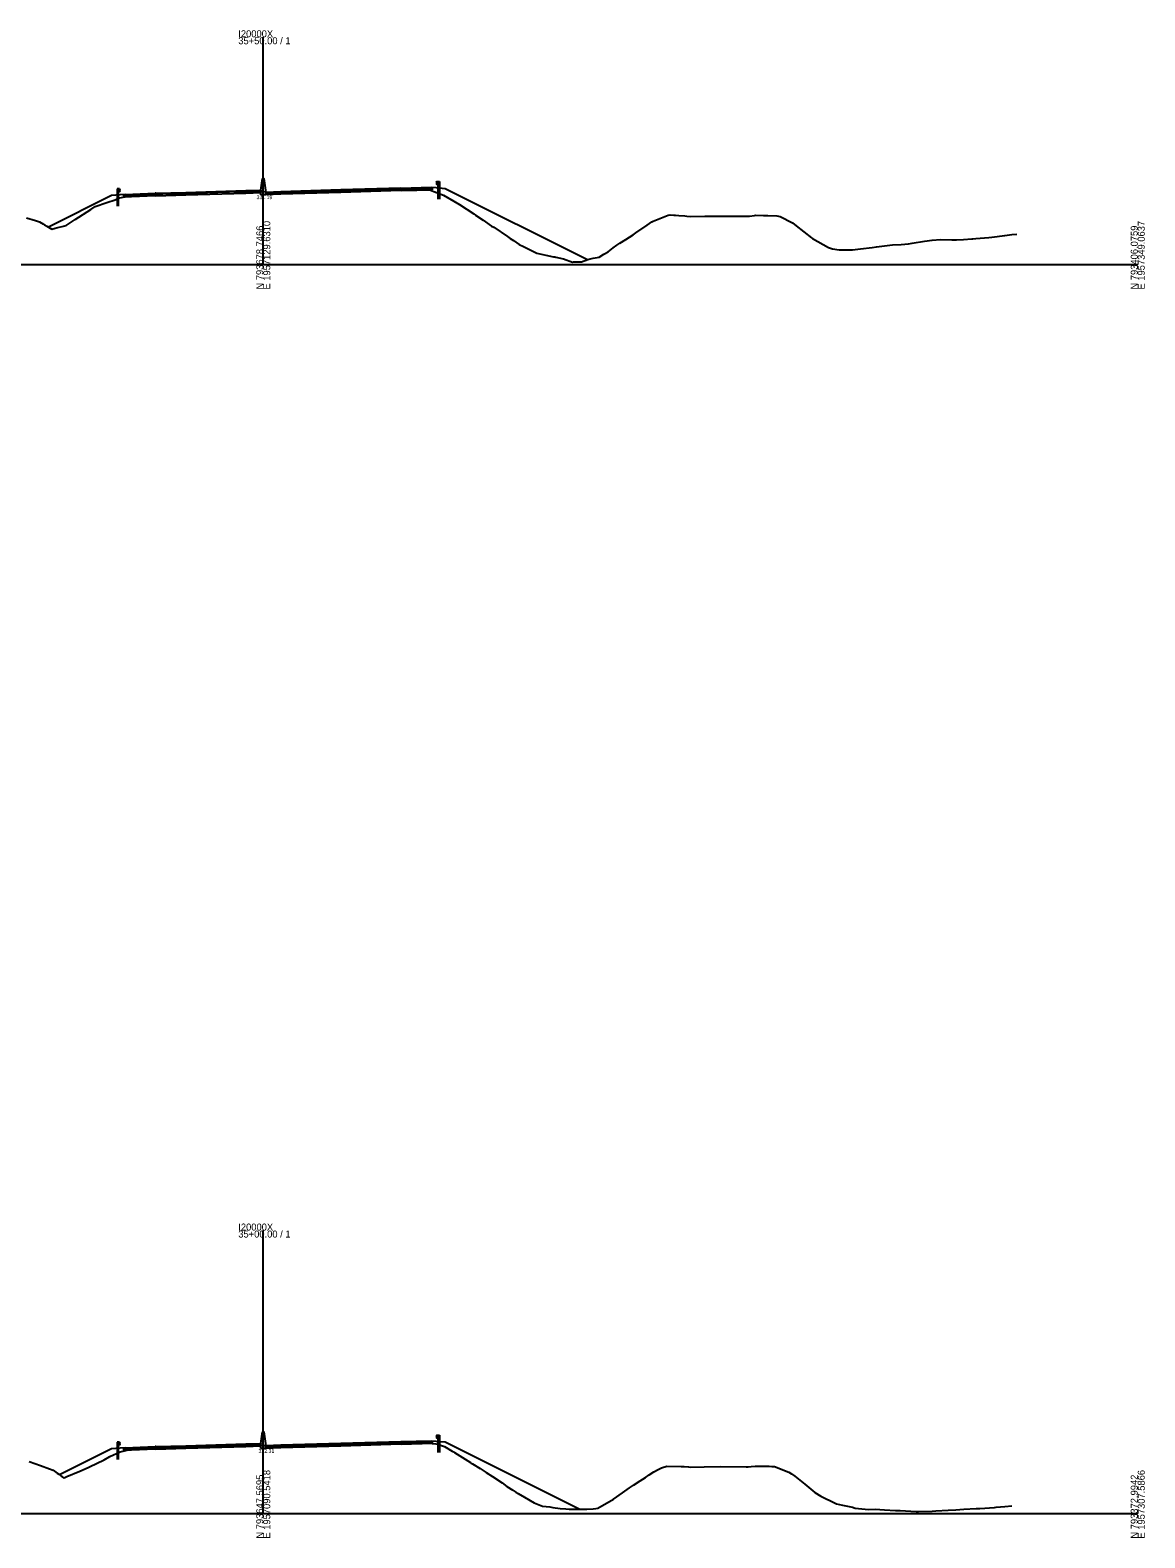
# Model space of a CAD drawing. Extents: x -4026 to 9638, y -10 to 19609.
# Drawn here: x -2743 to -2297, y 4990 to 5594 of the extents above; entities that cross this region are included whole.
import ezdxf

# ---------------------------------------------------------------- set-up
doc = ezdxf.new("R2010")
doc.units = 0
for name, color, linetype in [('RD_GPK_XS_Cell', 7, 'Continuous'), ('RD_XS_Base', 7, 'Continuous'), ('RD_XS_ExGround', 7, 'Continuous'), ('RD_XS_GR', 7, 'Continuous'), ('RD_XS_Greenside', 7, 'Continuous'), ('RD_XS_MedBWall', 7, 'Continuous'), ('RD_XS_Pave', 7, 'Continuous'), ('RD_XS_PaveOvlay', 7, 'Continuous'), ('RD_XS_TX_Elev_EX', 7, 'Continuous')]:
    doc.layers.add(name, color=color, linetype=linetype)

msp = doc.modelspace()

# ---------------------------------------------------------------- linework, layer by layer
at = {"layer": 'RD_GPK_XS_Cell'}
for p, q in [((-2650, 5500), (-2650, 5591)), ((-3000, 5500), (-2650, 5500)), ((-2650, 5500), (-2300, 5500)), ((-2650, 5000), (-2650, 5113.32)), ((-3000, 5000), (-2650, 5000)), ((-2650, 5000), (-2300, 5000))]:
    msp.add_line(p, q, dxfattribs=at)
at = {"layer": 'RD_XS_Base'}
for points in [[(-2657, 5529.29), (-2681, 5528.58), (-2693, 5528.21)], [(-2693, 5527.54), (-2681, 5527.91), (-2657, 5528.62)], [(-2651, 5529.48), (-2657, 5529.29)], [(-2657, 5529.29), (-2657, 5528.62)], [(-2657, 5528.62), (-2651, 5528.81)], [(-2651, 5528.81), (-2651, 5529.48)], [(-2649, 5528.58), (-2643, 5528.82)], [(-2649, 5527.91), (-2649, 5528.58)], [(-2643, 5528.82), (-2619, 5529.55), (-2595, 5530.26)], [(-2595, 5529.59), (-2619, 5528.88), (-2643, 5528.15)], [(-2643, 5528.15), (-2643, 5528.82)], [(-2595, 5530.26), (-2594.75, 5530.27)], [(-2595, 5529.59), (-2595, 5530.26)], [(-2594.75, 5529.6), (-2595, 5529.59)], [(-2582.25, 5530.65), (-2582.75, 5530.63), (-2594.75, 5530.27)], [(-2594.75, 5530.27), (-2594.75, 5529.6)], [(-2594.75, 5529.6), (-2582.25, 5529.98)], [(-2582.25, 5529.98), (-2582.25, 5530.65)], [(-2705.75, 5527.71), (-2705.25, 5527.73), (-2693.25, 5528.2)], [(-2705.75, 5527.04), (-2705.75, 5527.71)], [(-2693.25, 5527.53), (-2705.75, 5527.04)], [(-2693.25, 5528.2), (-2693, 5528.21)], [(-2693.25, 5527.53), (-2693.25, 5528.2)], [(-2693, 5527.54), (-2693.25, 5527.53)], [(-2693, 5528.21), (-2693, 5527.54)], [(-2643, 5528.15), (-2649, 5527.91)], [(-2657, 5027.57), (-2681, 5026.85), (-2693, 5026.48)], [(-2651, 5027.75), (-2657, 5027.57)], [(-2657, 5027.57), (-2657, 5026.9)], [(-2651, 5027.08), (-2651, 5027.75)], [(-2643, 5027.02), (-2619, 5027.74), (-2595, 5028.46)], [(-2595, 5027.79), (-2619, 5027.07), (-2643, 5026.35)], [(-2595, 5028.46), (-2594.75, 5028.47)], [(-2595, 5027.79), (-2595, 5028.46)], [(-2594.75, 5027.8), (-2595, 5027.79)], [(-2582.25, 5028.85), (-2582.75, 5028.83), (-2594.75, 5028.47)], [(-2594.75, 5028.47), (-2594.75, 5027.8)], [(-2594.75, 5027.8), (-2582.25, 5028.18)], [(-2582.25, 5028.18), (-2582.25, 5028.85)], [(-2705.75, 5025.98), (-2705.25, 5026), (-2693.25, 5026.48)], [(-2705.75, 5025.31), (-2705.75, 5025.98)], [(-2693.25, 5025.81), (-2705.75, 5025.31)], [(-2693.25, 5026.48), (-2693, 5026.48)], [(-2693.25, 5025.81), (-2693.25, 5026.48)], [(-2693, 5025.81), (-2693.25, 5025.81)], [(-2693, 5025.81), (-2681, 5026.18), (-2657, 5026.9)], [(-2693, 5026.48), (-2693, 5025.81)], [(-2657, 5026.9), (-2651, 5027.08)], [(-2649, 5026.78), (-2643, 5027.02)], [(-2649, 5026.11), (-2649, 5026.78)], [(-2643, 5026.35), (-2649, 5026.11)], [(-2643, 5026.35), (-2643, 5027.02)]]:
    msp.add_lwpolyline(points, dxfattribs=at)
at = {"layer": 'RD_XS_ExGround'}
for points in [[(-2744.73, 5518.7), (-2741.2, 5517.64), (-2739.6, 5517.08), (-2737.97, 5516.17), (-2737.5, 5515.88), (-2736.65, 5515.37), (-2734.57, 5514.12), (-2733.26, 5514.52), (-2728.94, 5515.68), (-2725.25, 5518), (-2719.06, 5522.08), (-2717.28, 5523.25), (-2712.64, 5524.9), (-2709.3, 5525.9), (-2707.6, 5526.75), (-2704.43, 5527.23), (-2703.33, 5527.4), (-2700.91, 5527.8), (-2700.05, 5527.93), (-2692.06, 5528.25), (-2690.7, 5528.3), (-2690.19, 5528.31), (-2679.86, 5528.61), (-2672.38, 5528.86), (-2668.24, 5528.99), (-2665.63, 5529.06), (-2663.5, 5529.11), (-2656.48, 5529.29), (-2654.34, 5529.28), (-2650.92, 5529.27), (-2650, 5529.19), (-2647.75, 5528.98), (-2646.99, 5528.9), (-2645.36, 5529.01), (-2641.8, 5529.23), (-2639.49, 5529.31), (-2638.29, 5529.35), (-2637.76, 5529.37), (-2637.46, 5529.38), (-2635.63, 5529.44), (-2630.32, 5529.55), (-2629.82, 5529.56), (-2618.59, 5529.87), (-2607.58, 5530.16), (-2603.85, 5530.22), (-2598.52, 5530.31), (-2592.56, 5530.33), (-2590.25, 5530.33), (-2588.86, 5530.22), (-2586.68, 5530.04), (-2585.73, 5529.98), (-2583.13, 5529.78), (-2581.7, 5529.31), (-2577.87, 5527.77), (-2573.73, 5525.43), (-2571.45, 5524.05), (-2565.75, 5520.29), (-2565.03, 5519.79), (-2562.05, 5517.8), (-2558.61, 5515.41), (-2557.78, 5514.98), (-2552.19, 5511.29), (-2551.13, 5510.5), (-2549.8, 5509.58), (-2547.57, 5508.05), (-2545.78, 5507.2), (-2544.02, 5506.35), (-2541.83, 5505.26), (-2540.46, 5504.61), (-2539.36, 5504.31), (-2536.9, 5503.72), (-2533.85, 5503.16), (-2533.35, 5503.07), (-2532.94, 5502.97), (-2529.79, 5502.29), (-2526.23, 5501.01), (-2525.88, 5501.06), (-2522.68, 5501.04), (-2520.1, 5502), (-2519.12, 5502.27), (-2517.9, 5502.56), (-2515.57, 5503.01), (-2513.69, 5504.13), (-2512.01, 5505.15), (-2509.93, 5506.74), (-2508.45, 5507.83), (-2507.27, 5508.52), (-2504.9, 5510.03), (-2501.95, 5511.97), (-2500.85, 5512.74), (-2496.31, 5515.8), (-2494.43, 5517.07), (-2493.98, 5517.35), (-2488.01, 5519.74), (-2487.12, 5519.86), (-2485.62, 5519.76), (-2485.01, 5519.73), (-2483.67, 5519.62), (-2481.27, 5519.48), (-2480.42, 5519.41), (-2478.88, 5519.26), (-2473.33, 5519.34), (-2466.87, 5519.44), (-2458.55, 5519.36), (-2455.44, 5519.34), (-2453.43, 5519.67), (-2452.82, 5519.76), (-2449.77, 5519.67), (-2448.11, 5519.66), (-2444.44, 5519.58), (-2443.09, 5519.25), (-2438.15, 5516.76), (-2436.67, 5515.57), (-2430.57, 5510.73), (-2430.18, 5510.42), (-2423.83, 5506.84), (-2422.2, 5506.3), (-2419.55, 5505.91), (-2417.42, 5505.85), (-2414.23, 5505.96), (-2411, 5506.33), (-2406.25, 5506.88), (-2404.58, 5507.15), (-2398.16, 5507.85), (-2394.66, 5508.09), (-2391.74, 5508.34), (-2390.3, 5508.53), (-2385.33, 5509.33), (-2382.32, 5509.82), (-2378.91, 5510), (-2374.35, 5509.87), (-2372.49, 5509.93), (-2369.76, 5510.05), (-2366.37, 5510.33), (-2366.07, 5510.35), (-2364.82, 5510.46), (-2359.65, 5510.88), (-2358.4, 5510.99), (-2353.24, 5511.7), (-2350.42, 5512.04), (-2348.43, 5512.23)], [(-2743.68, 5020.83), (-2739.2, 5019.28), (-2735.61, 5017.89), (-2734.06, 5017.34), (-2732.46, 5016.21), (-2731.87, 5015.75), (-2730.56, 5014.93), (-2729.71, 5014.37), (-2728.67, 5014.81), (-2723.38, 5016.98), (-2720.08, 5018.53), (-2719.49, 5018.8), (-2713.71, 5021.6), (-2711.43, 5022.82), (-2707.34, 5024.78), (-2703.28, 5025.7), (-2702.52, 5025.81), (-2700.97, 5026.03), (-2700.06, 5026.15), (-2692.95, 5026.4), (-2690.99, 5026.46), (-2687.96, 5026.56), (-2680.17, 5026.82), (-2673.05, 5027.04), (-2668.39, 5027.17), (-2666.24, 5027.23), (-2656.66, 5027.48), (-2654.76, 5027.46), (-2651.19, 5027.42), (-2650, 5027.31), (-2649.11, 5027.23), (-2647.24, 5027.07), (-2644.34, 5027.25), (-2642.08, 5027.39), (-2641.37, 5027.42), (-2634.39, 5027.65), (-2631.13, 5027.72), (-2630.17, 5027.74), (-2628.16, 5027.8), (-2618.98, 5028.07), (-2615.3, 5028.17), (-2607.79, 5028.34), (-2599.96, 5028.49), (-2598.43, 5028.52), (-2597, 5028.53), (-2590.45, 5028.56), (-2589.33, 5028.48), (-2587.96, 5028.4), (-2584.55, 5028.19), (-2582.42, 5028.06), (-2580.99, 5027.98), (-2579.87, 5027.65), (-2577.43, 5026.83), (-2574.36, 5025.01), (-2573.87, 5024.73), (-2573.49, 5024.48), (-2570.32, 5022.48), (-2567.12, 5020.47), (-2566.76, 5020.25), (-2566.29, 5019.95), (-2563.2, 5018.1), (-2560.75, 5016.4), (-2558.23, 5014.85), (-2554.37, 5012.29), (-2552.52, 5010.86), (-2550.17, 5009.34), (-2548.96, 5008.6), (-2548, 5008.08), (-2545.4, 5006.59), (-2541.63, 5004.26), (-2538.28, 5003.05), (-2535.25, 5002.67), (-2534.04, 5002.51), (-2531.16, 5002.1), (-2528.88, 5001.96), (-2527.6, 5001.81), (-2525.98, 5001.79), (-2522.51, 5001.73), (-2520.48, 5001.8), (-2517.92, 5001.87), (-2516.92, 5002.01), (-2516.13, 5002.2), (-2509.76, 5005.84), (-2506.24, 5008.34), (-2503.39, 5010.39), (-2502.68, 5010.85), (-2501.79, 5011.43), (-2499.12, 5013.1), (-2497.01, 5014.53), (-2495.56, 5015.49), (-2493.73, 5016.69), (-2492, 5017.73), (-2490.64, 5018.31), (-2488.44, 5019), (-2482.69, 5018.93), (-2481.5, 5018.93), (-2479.85, 5018.75), (-2479.09, 5018.66), (-2473.47, 5018.75), (-2467.1, 5018.86), (-2456.68, 5018.78), (-2455.87, 5018.77), (-2454.7, 5018.87), (-2453.06, 5019.01), (-2451.66, 5018.99), (-2447.47, 5018.95), (-2446.47, 5018.93), (-2445.73, 5018.92), (-2445.35, 5018.83), (-2439.65, 5016.63), (-2438.61, 5015.93), (-2437.29, 5014.94), (-2433.28, 5011.8), (-2429.23, 5008.47), (-2426.9, 5007.01), (-2421.16, 5004.2), (-2420.53, 5003.89), (-2418.14, 5003.41), (-2414.16, 5002.54), (-2413.1, 5002.24), (-2407.78, 5001.61), (-2405.04, 5001.73), (-2401.41, 5001.54), (-2396.97, 5001.31), (-2395.04, 5001.22), (-2388.66, 5000.85), (-2387.72, 5000.87), (-2382.29, 5000.94), (-2380.85, 5001.08), (-2375.92, 5001.45), (-2372.79, 5001.56), (-2369.54, 5001.84), (-2364.72, 5002.03), (-2363.17, 5002.08), (-2357.3, 5002.48), (-2356.66, 5002.53), (-2353.18, 5002.83), (-2350.42, 5003.15)]]:
    msp.add_lwpolyline(points, dxfattribs=at)
at = {"layer": 'RD_XS_GR'}
for points in [[(-2707.98, 5530.3), (-2708.48, 5530.3)], [(-2708.48, 5530.3), (-2708.48, 5527.8)], [(-2707.98, 5527.84), (-2707.98, 5530.3)], [(-2707.49, 5530.3), (-2707.98, 5530.3)], [(-2707.98, 5530.3), (-2707.98, 5529.12)], [(-2707.98, 5529.12), (-2707.49, 5529.12)], [(-2707.49, 5530.3), (-2707.25, 5530)], [(-2707.49, 5529.12), (-2707.49, 5530.3)], [(-2707.25, 5529.42), (-2707.49, 5529.12)], [(-2707.25, 5530), (-2707.48, 5529.7)], [(-2707.48, 5529.7), (-2707.25, 5529.42)], [(-2580.51, 5533.2), (-2580.75, 5532.9)], [(-2580.75, 5532.9), (-2580.52, 5532.6)], [(-2580.52, 5532.6), (-2580.75, 5532.32)], [(-2580.75, 5532.32), (-2580.51, 5532.02)], [(-2580.51, 5532.02), (-2580.51, 5533.2)], [(-2580.51, 5533.2), (-2580.02, 5533.2)], [(-2580.02, 5532.02), (-2580.51, 5532.02)], [(-2580.02, 5533.2), (-2579.52, 5533.2)], [(-2580.02, 5530.74), (-2580.02, 5533.2)], [(-2580.02, 5533.2), (-2580.02, 5532.02)], [(-2580.02, 5526.24), (-2580.02, 5530.74)], [(-2580.02, 5530.74), (-2579.52, 5530.7)], [(-2579.52, 5530.7), (-2580.02, 5530.74)], [(-2579.52, 5533.2), (-2579.52, 5530.7)], [(-2579.52, 5530.7), (-2579.52, 5526.24)], [(-2707.98, 5527.84), (-2708.48, 5527.8)], [(-2708.48, 5527.8), (-2707.98, 5527.84)], [(-2708.48, 5527.8), (-2708.48, 5523.34)], [(-2707.98, 5523.34), (-2707.98, 5527.84)], [(-2707.98, 5028.58), (-2708.48, 5028.58)], [(-2708.48, 5028.58), (-2708.48, 5026.08)], [(-2707.98, 5026.12), (-2707.98, 5028.58)], [(-2707.49, 5028.58), (-2707.98, 5028.58)], [(-2707.98, 5028.58), (-2707.98, 5027.4)], [(-2707.49, 5028.58), (-2707.25, 5028.28)], [(-2707.49, 5027.4), (-2707.49, 5028.58)], [(-2707.25, 5027.7), (-2707.49, 5027.4)], [(-2707.25, 5028.28), (-2707.48, 5027.98)], [(-2707.48, 5027.98), (-2707.25, 5027.7)], [(-2580.51, 5031.4), (-2580.75, 5031.1)], [(-2580.75, 5031.1), (-2580.52, 5030.8)], [(-2580.52, 5030.8), (-2580.75, 5030.52)], [(-2580.75, 5030.52), (-2580.51, 5030.22)], [(-2580.51, 5030.22), (-2580.51, 5031.4)], [(-2580.51, 5031.4), (-2580.02, 5031.4)], [(-2580.02, 5030.22), (-2580.51, 5030.22)], [(-2580.02, 5031.4), (-2579.52, 5031.4)], [(-2580.02, 5028.94), (-2580.02, 5031.4)], [(-2580.02, 5031.4), (-2580.02, 5030.22)], [(-2580.02, 5024.44), (-2580.02, 5028.94)], [(-2580.02, 5028.94), (-2579.52, 5028.9)], [(-2579.52, 5028.9), (-2580.02, 5028.94)], [(-2579.52, 5031.4), (-2579.52, 5028.9)], [(-2579.52, 5028.9), (-2579.52, 5024.44)], [(-2707.98, 5026.12), (-2708.48, 5026.08)], [(-2708.48, 5026.08), (-2707.98, 5026.12)], [(-2708.48, 5026.08), (-2708.48, 5021.62)], [(-2707.98, 5027.4), (-2707.49, 5027.4)], [(-2707.98, 5021.62), (-2707.98, 5026.12)]]:
    msp.add_lwpolyline(points, dxfattribs=at)
at = {"layer": 'RD_XS_Greenside'}
for points in [[(-2582.75, 5530.97), (-2580.75, 5530.8)], [(-2580.75, 5530.8), (-2577.25, 5530.51), (-2520.18, 5501.97)], [(-2707.25, 5527.9), (-2710.75, 5527.62), (-2736.01, 5514.99)], [(-2705.25, 5528.06), (-2707.25, 5527.9)], [(-2582.75, 5029.17), (-2580.75, 5029)], [(-2580.75, 5029), (-2577.25, 5028.71), (-2523.33, 5001.75)], [(-2707.25, 5026.18), (-2710.75, 5025.9), (-2731.5, 5015.52)], [(-2705.25, 5026.34), (-2707.25, 5026.18)]]:
    msp.add_lwpolyline(points, dxfattribs=at)
at = {"layer": 'RD_XS_MedBWall'}
for points in [[(-2651, 5529.81), (-2650.25, 5534.48)], [(-2650.25, 5534.48), (-2649.75, 5534.48), (-2649, 5528.91)], [(-2651, 5527.91), (-2651, 5529.48), (-2651, 5529.81)], [(-2649, 5528.91), (-2649, 5528.58), (-2649, 5527.91)], [(-2649, 5527.91), (-2651, 5527.91)], [(-2651, 5028.08), (-2650.25, 5032.75)], [(-2651, 5026.11), (-2651, 5027.75), (-2651, 5028.08)], [(-2650.25, 5032.75), (-2649.75, 5032.75), (-2649, 5027.11)], [(-2649, 5026.11), (-2651, 5026.11)], [(-2649, 5027.11), (-2649, 5026.78), (-2649, 5026.11)]]:
    msp.add_lwpolyline(points, dxfattribs=at)
at = {"layer": 'RD_XS_Pave'}
for points in [[(-2693, 5528.38), (-2681, 5528.74), (-2657, 5529.46)], [(-2657, 5529.29), (-2681, 5528.58), (-2693, 5528.21)], [(-2657, 5529.46), (-2651, 5529.65)], [(-2651, 5529.48), (-2657, 5529.29)], [(-2657, 5529.46), (-2657, 5529.29)], [(-2651, 5529.65), (-2651, 5529.48)], [(-2643, 5528.99), (-2649, 5528.75)], [(-2649, 5528.58), (-2643, 5528.82)], [(-2649, 5528.75), (-2649, 5528.58)], [(-2595, 5530.43), (-2619, 5529.71), (-2643, 5528.99)], [(-2643, 5528.82), (-2619, 5529.55), (-2595, 5530.26)], [(-2643, 5528.99), (-2643, 5528.82)], [(-2595, 5530.43), (-2594.75, 5530.44)], [(-2595, 5530.26), (-2595, 5530.43)], [(-2594.75, 5530.27), (-2595, 5530.26)], [(-2582.75, 5530.8), (-2594.75, 5530.44)], [(-2594.75, 5530.27), (-2582.75, 5530.63)], [(-2594.75, 5530.44), (-2594.75, 5530.27)], [(-2582.75, 5530.63), (-2582.75, 5530.8)], [(-2705.25, 5527.89), (-2693.25, 5528.37)], [(-2693.25, 5528.2), (-2705.25, 5527.73)], [(-2705.25, 5527.73), (-2705.25, 5527.89)], [(-2693.25, 5528.37), (-2693, 5528.38)], [(-2693.25, 5528.2), (-2693.25, 5528.37)], [(-2693, 5528.21), (-2693.25, 5528.2)], [(-2693, 5528.38), (-2693, 5528.21)], [(-2693, 5026.65), (-2681, 5027.02), (-2657, 5027.74)], [(-2657, 5027.57), (-2681, 5026.85), (-2693, 5026.48)], [(-2657, 5027.74), (-2651, 5027.92)], [(-2651, 5027.75), (-2657, 5027.57)], [(-2657, 5027.74), (-2657, 5027.57)], [(-2651, 5027.92), (-2651, 5027.75)], [(-2595, 5028.63), (-2619, 5027.91), (-2643, 5027.19)], [(-2643, 5027.02), (-2619, 5027.74), (-2595, 5028.46)], [(-2595, 5028.63), (-2594.75, 5028.64)], [(-2595, 5028.46), (-2595, 5028.63)], [(-2594.75, 5028.47), (-2595, 5028.46)], [(-2582.75, 5029), (-2594.75, 5028.64)], [(-2594.75, 5028.47), (-2582.75, 5028.83)], [(-2594.75, 5028.64), (-2594.75, 5028.47)], [(-2582.75, 5028.83), (-2582.75, 5029)], [(-2705.25, 5026.17), (-2693.25, 5026.65)], [(-2693.25, 5026.48), (-2705.25, 5026)], [(-2705.25, 5026), (-2705.25, 5026.17)], [(-2693.25, 5026.65), (-2693, 5026.65)], [(-2693.25, 5026.48), (-2693.25, 5026.65)], [(-2693, 5026.48), (-2693.25, 5026.48)], [(-2693, 5026.65), (-2693, 5026.48)], [(-2643, 5027.19), (-2649, 5026.95)], [(-2649, 5026.78), (-2643, 5027.02)], [(-2649, 5026.95), (-2649, 5026.78)], [(-2643, 5027.19), (-2643, 5027.02)]]:
    msp.add_lwpolyline(points, dxfattribs=at)
at = {"layer": 'RD_XS_PaveOvlay'}
for points in [[(-2705.25, 5528.06), (-2693.25, 5528.54)], [(-2693, 5528.55), (-2693.25, 5528.54)], [(-2693.25, 5528.54), (-2693.25, 5528.37)], [(-2693, 5528.55), (-2681, 5528.91), (-2657, 5529.63)], [(-2657, 5529.46), (-2681, 5528.74), (-2693, 5528.38)], [(-2693, 5528.38), (-2693, 5528.55)], [(-2657, 5529.63), (-2651, 5529.81)], [(-2651, 5529.65), (-2657, 5529.46)], [(-2657, 5529.63), (-2657, 5529.46)], [(-2651, 5529.81), (-2651, 5529.65)], [(-2643, 5529.16), (-2649, 5528.91)], [(-2649, 5528.75), (-2643, 5528.99)], [(-2649, 5528.91), (-2649, 5528.75)], [(-2595, 5530.6), (-2619, 5529.88), (-2643, 5529.16)], [(-2643, 5528.99), (-2619, 5529.71), (-2595, 5530.43)], [(-2643, 5529.16), (-2643, 5528.99)], [(-2595, 5530.6), (-2594.75, 5530.61)], [(-2595, 5530.43), (-2595, 5530.6)], [(-2594.75, 5530.44), (-2595, 5530.43)], [(-2594.75, 5530.61), (-2582.75, 5530.97)], [(-2582.75, 5530.8), (-2594.75, 5530.44)], [(-2594.75, 5530.61), (-2594.75, 5530.44)], [(-2582.75, 5530.97), (-2582.75, 5530.8)], [(-2693.25, 5528.37), (-2705.25, 5527.89)], [(-2705.25, 5527.89), (-2705.25, 5528.06)], [(-2693.25, 5528.37), (-2693, 5528.38)], [(-2693, 5026.82), (-2681, 5027.18), (-2657, 5027.9)], [(-2657, 5027.74), (-2681, 5027.02), (-2693, 5026.65)], [(-2657, 5027.9), (-2651, 5028.08)], [(-2651, 5027.92), (-2657, 5027.74)], [(-2657, 5027.9), (-2657, 5027.74)], [(-2651, 5028.08), (-2651, 5027.92)], [(-2595, 5028.8), (-2619, 5028.08), (-2643, 5027.36)], [(-2643, 5027.19), (-2619, 5027.91), (-2595, 5028.63)], [(-2595, 5028.8), (-2594.75, 5028.81)], [(-2595, 5028.63), (-2595, 5028.8)], [(-2594.75, 5028.64), (-2595, 5028.63)], [(-2594.75, 5028.81), (-2582.75, 5029.17)], [(-2582.75, 5029), (-2594.75, 5028.64)], [(-2594.75, 5028.81), (-2594.75, 5028.64)], [(-2582.75, 5029.17), (-2582.75, 5029)], [(-2705.25, 5026.34), (-2693.25, 5026.82)], [(-2693.25, 5026.65), (-2705.25, 5026.17)], [(-2705.25, 5026.17), (-2705.25, 5026.34)], [(-2693.25, 5026.82), (-2693.25, 5026.65)], [(-2693, 5026.82), (-2693.25, 5026.82)], [(-2693.25, 5026.65), (-2693, 5026.65)], [(-2693, 5026.65), (-2693, 5026.82)], [(-2643, 5027.36), (-2649, 5027.11)], [(-2649, 5026.95), (-2643, 5027.19)], [(-2649, 5027.11), (-2649, 5026.95)], [(-2643, 5027.36), (-2643, 5027.19)]]:
    msp.add_lwpolyline(points, dxfattribs=at)

# ---------------------------------------------------------------- texts
at = {"layer": 'RD_GPK_XS_Cell'}
for s, p in [('35+50.00 / 1', (-2660, 5588.2)), ('I20000X', (-2660, 5591)), ('35+00.00 / 1', (-2660, 5110.52)), ('I20000X', (-2660, 5113.32))]:
    msp.add_text(s, height=2.8, dxfattribs=at).set_placement(p)
for s, p in [('E 1957129.6310', (-2647.2, 5490)), ('E 1957349.0637', (-2297.2, 5490)), ('N 793678.7466', (-2650, 5490)), ('N 793406.0759', (-2300, 5490)), ('N 793647.5695', (-2650, 4990)), ('E 1957090.5418', (-2647.2, 4990)), ('N 793372.9942', (-2300, 4990)), ('E 1957307.5866', (-2297.2, 4990))]:
    msp.add_text(s, height=2.8, rotation=90, dxfattribs=at).set_placement(p)
at = {"layer": 'RD_XS_TX_Elev_EX'}
for s, p in [('331.19', (-2652.69, 5526.19)), ('332.31', (-2651.91, 5024.31))]:
    msp.add_text(s, height=1.5, dxfattribs=at).set_placement(p)

doc.saveas('drawing.dxf')
